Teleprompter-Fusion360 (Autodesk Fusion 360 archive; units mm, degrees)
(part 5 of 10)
sketch "Skizze56" plane through (0, 0, 0) normal (0, 0, -1) x axis (1, 0, 0)
  line L1 (-2.9969, -220.3404) -> (-2.9968, -220.3404)
  line L2 (-2.9969, -235.9451) -> (-2.9969, -220.3404)
  line L3 (-14.9969, -240.1877) -> (-7.2396, -240.1877)
  line L4 (-14.9969, -255.3404) -> (-14.9969, -240.1877)
  line L5 (374.0031, -255.3404) -> (-14.9969, -255.3404)
  line L6 (374.0031, -240.1877) -> (374.0031, -255.3404)
  line L7 (366.2457, -240.1877) -> (374.0031, -240.1877)
  line L8 (362.0031, -220.3404) -> (362.0031, -235.9451)
  line L9 (361.0031, -220.3404) -> (362.0031, -220.3404)
  line L10 (358.0031, -167.3404) -> (358.0031, -217.3404)
  line L11 (362.0031, -164.3404) -> (361.0031, -164.3404)
  line L12 (362.0031, -134.383) -> (362.0031, -164.3404)
  line L13 (374.0031, -130.1404) -> (366.2457, -130.1404)
  line L14 (374.0031, -95.9404) -> (374.0031, -130.1404)
  line L15 (366.2457, -95.9404) -> (374.0031, -95.9404)
  line L16 (362.0031, -65.983) -> (362.0031, -91.6977)
  line L17 (374.0031, -61.7404) -> (366.2457, -61.7404)
  line L18 (374.0031, -27.5404) -> (374.0031, -61.7404)
  line L19 (366.2457, -27.5404) -> (374.0031, -27.5404)
  line L20 (362.0031, 2.417) -> (362.0031, -23.2977)
  line L21 (374.0031, 6.6596) -> (366.2457, 6.6596)
  line L22 (-2.9969, 18.6596) -> (362.0031, 18.6596)
  line L23 (-7.2396, 6.6596) -> (-14.9969, 6.6596)
  line L24 (-2.9969, -23.2977) -> (-2.9969, 2.417)
  line L25 (-14.9969, -27.5404) -> (-7.2396, -27.5404)
  line L26 (-14.9969, -61.7404) -> (-14.9969, -27.5404)
  line L27 (-7.2396, -61.7404) -> (-14.9969, -61.7404)
  line L28 (-2.9969, -91.6977) -> (-2.9969, -65.983)
  line L29 (-14.9969, -95.9404) -> (-7.2396, -95.9404)
  line L30 (-14.9969, -130.1404) -> (-14.9969, -95.9404)
  line L31 (-7.2396, -130.1404) -> (-14.9969, -130.1404)
  line L32 (-2.9969, -164.3404) -> (-2.9969, -134.383)
  line L33 (-2.9968, -164.3404) -> (-2.9969, -164.3404)
  line L34 (0.0031, -217.3404) -> (0.0031, -167.3404)
  line L35 (300.0031, -190.3404) -> (300.0031, -174.3404)
  line L36 (203.5031, -202.3404) -> (288.0031, -202.3404)
  line L37 (191.5031, -174.3404) -> (191.5031, -190.3404)
  line L38 (288.0031, -162.3404) -> (203.5031, -162.3404)
  line L39 (191.5031, -31.3404) -> (191.5031, -114.3404)
  line L40 (312.0031, -19.3404) -> (203.5031, -19.3404)
  line L41 (324.0031, -114.3404) -> (324.0031, -31.3404)
  line L42 (203.5031, -126.3404) -> (312.0031, -126.3404)
  line L43 (71.0031, -202.3404) -> (155.5031, -202.3404)
  line L44 (59.0031, -174.3404) -> (59.0031, -190.3404)
  line L45 (155.5031, -162.3404) -> (71.0031, -162.3404)
  line L46 (167.5031, -190.3404) -> (167.5031, -174.3404)
  line L47 (47.0031, -126.3404) -> (155.5031, -126.3404)
  line L48 (35.0031, -31.3404) -> (35.0031, -114.3404)
  line L49 (155.5031, -19.3404) -> (47.0031, -19.3404)
  line L50 (167.5031, -114.3404) -> (167.5031, -31.3404)
  line L51 (-2.9969, -258.4937) -> (-2.9969, -220.3404)
  line L52 (-2.9969, -255.3404) -> (-14.9969, -255.3404)
  line L53 (-2.9969, -240.1877) -> (-2.9969, -255.3404)
  line L54 (-14.9969, -240.1877) -> (-2.9969, -240.1877)
  line L55 (-14.9969, -255.3404) -> (-14.9969, -240.1877)
  line L56 (362.0031, -255.3404) -> (362.0031, -235.9451)
  line L57 (374.0031, -240.1877) -> (362.0031, -240.1877)
  line L58 (374.0031, -255.3404) -> (374.0031, -240.1877)
  line L59 (362.0031, -255.3404) -> (374.0031, -255.3404)
  line L60 (362.0031, -240.1877) -> (362.0031, -255.3404)
  line L61 (368.0031, -240.1877) -> (368.0031, -255.3404)
  line L62 (-8.9969, -240.1877) -> (-8.9969, -255.3404)
  arc A1 centre (-5.1183, -238.0664) radius 3 clockwise from (-2.9969, -235.9451) to (-7.2396, -240.1877)
  arc A2 centre (364.1244, -238.0664) radius 3 clockwise from (366.2457, -240.1877) to (362.0031, -235.9451)
  arc A3 centre (361.0031, -217.3404) radius 3 clockwise from (361.0031, -220.3404) to (358.0031, -217.3404)
  arc A4 centre (361.0031, -167.3404) radius 3 clockwise from (358.0031, -167.3404) to (361.0031, -164.3404)
  arc A5 centre (364.1244, -132.2617) radius 3 clockwise from (362.0031, -134.383) to (366.2457, -130.1404)
  arc A6 centre (364.1244, -93.8191) radius 3 clockwise from (366.2457, -95.9404) to (362.0031, -91.6977)
  arc A7 centre (364.1244, -63.8617) radius 3 clockwise from (362.0031, -65.983) to (366.2457, -61.7404)
  arc A8 centre (364.1244, -25.4191) radius 3 clockwise from (366.2457, -27.5404) to (362.0031, -23.2977)
  arc A9 centre (364.1244, 4.5383) radius 3 clockwise from (362.0031, 2.417) to (366.2457, 6.6596)
  arc A10 centre (362.0031, 6.6596) radius 12 clockwise from (362.0031, 18.6596) to (374.0031, 6.6596)
  arc A11 centre (-2.9969, 6.6596) radius 12 clockwise from (-14.9969, 6.6596) to (-2.9969, 18.6596)
  arc A12 centre (-5.1183, 4.5383) radius 3 clockwise from (-7.2396, 6.6596) to (-2.9969, 2.417)
  arc A13 centre (-5.1183, -25.4191) radius 3 clockwise from (-2.9969, -23.2977) to (-7.2396, -27.5404)
  arc A14 centre (-5.1183, -63.8617) radius 3 clockwise from (-7.2396, -61.7404) to (-2.9969, -65.983)
  arc A15 centre (-5.1183, -93.8191) radius 3 clockwise from (-2.9969, -91.6977) to (-7.2396, -95.9404)
  arc A16 centre (-5.1183, -132.2617) radius 3 clockwise from (-7.2396, -130.1404) to (-2.9969, -134.383)
  arc A17 centre (-2.9969, -167.3404) radius 3 clockwise from (-2.9968, -164.3404) to (0.0031, -167.3404)
  arc A18 centre (-2.9969, -217.3404) radius 3 clockwise from (0.0031, -217.3404) to (-2.9968, -220.3404)
  circle C1 centre (-8.9969, -44.6404) radius 1.5
  circle C2 centre (368.0031, -44.6404) radius 1.5
  arc A19 centre (288.0031, -190.3404) radius 12 clockwise from (300.0031, -190.3404) to (288.0031, -202.3404)
  arc A20 centre (203.5031, -190.3404) radius 12 clockwise from (203.5031, -202.3404) to (191.5031, -190.3404)
  arc A21 centre (203.5031, -174.3404) radius 12 clockwise from (191.5031, -174.3404) to (203.5031, -162.3404)
  arc A22 centre (288.0031, -174.3404) radius 12 clockwise from (288.0031, -162.3404) to (300.0031, -174.3404)
  arc A23 centre (203.5031, -31.3404) radius 12 clockwise from (191.5031, -31.3404) to (203.5031, -19.3404)
  arc A24 centre (312.0031, -31.3404) radius 12 clockwise from (312.0031, -19.3404) to (324.0031, -31.3404)
  arc A25 centre (312.0031, -114.3404) radius 12 clockwise from (324.0031, -114.3404) to (312.0031, -126.3404)
  arc A26 centre (203.5031, -114.3404) radius 12 clockwise from (203.5031, -126.3404) to (191.5031, -114.3404)
  arc A27 centre (71.0031, -190.3404) radius 12 clockwise from (71.0031, -202.3404) to (59.0031, -190.3404)
  arc A28 centre (71.0031, -174.3404) radius 12 clockwise from (59.0031, -174.3404) to (71.0031, -162.3404)
  arc A29 centre (155.5031, -174.3404) radius 12 clockwise from (155.5031, -162.3404) to (167.5031, -174.3404)
  arc A30 centre (155.5031, -190.3404) radius 12 clockwise from (167.5031, -190.3404) to (155.5031, -202.3404)
  arc A31 centre (47.0031, -114.3404) radius 12 clockwise from (47.0031, -126.3404) to (35.0031, -114.3404)
  arc A32 centre (47.0031, -31.3404) radius 12 clockwise from (35.0031, -31.3404) to (47.0031, -19.3404)
  arc A33 centre (155.5031, -31.3404) radius 12 clockwise from (155.5031, -19.3404) to (167.5031, -31.3404)
  arc A34 centre (155.5031, -114.3404) radius 12 clockwise from (167.5031, -114.3404) to (155.5031, -126.3404)
  circle C3 centre (368.0031, -113.0404) radius 1.5
  circle C4 centre (-8.9969, -113.0404) radius 1.5
  circle C5 centre (-8.9969, -246.1877) radius 1.5
  circle C6 centre (368.0031, -246.1877) radius 1.5
  point P3 (-2.9969, -220.3404)
  point P124 (-2.9969, -220.3404)
  point P128 (-2.9969, -240.1877)
  point P8 (-14.9969, -255.3404)
  point P126 (-14.9969, -255.3404)
  point P12 (362.0031, -235.9451)
  point P130 (362.0031, -235.9451)
  point P9 (374.0031, -255.3404)
  point P133 (374.0031, -255.3404)
  point P131 (362.0031, -240.1877)
  point P135 (368.0031, -255.3404)
  point P136 (368.0031, -240.1877)
  point P137 (-8.9969, -255.3404)
  point P138 (-8.9969, -240.1877)
  point P139 (-8.9969, -246.1877)
  point P140 (368.0031, -246.1877)
  coincident P3 P124
  perpendicular L5 L51
  horizontal L52
  vertical L53
  horizontal L54
  vertical L55
  midpoint A1 P128
  coincident P8 P126
  coincident P12 P130
  perpendicular L5 L56
  horizontal L57
  vertical L58
  horizontal L59
  vertical L60
  coincident P9 P133
  midpoint A2 P131
  midpoint L59 P135
  midpoint L57 P136
  midpoint L52 P137
  midpoint L54 P138
  coincident L62 P139
  coincident L61 P140
  dimension "d331" diameter C5 = 3
  dimension "d332" diameter C6 = 3
  dimension "d333" distance L57 P140 = 6
  dimension "d334" distance L54 P139 = 6
extrude "Extrusion56" cut sketch "Skizze56" profile of C5 C6 against normal blind 12
sketch "Skizze57" plane through (-14.9969, 0, 0) normal (-1, 0, 0) x axis (0, -1, 0)
  line L1 (-156.4445, 183.2864) -> (-195.6625, 104.4333)
  line L2 (-133.7, 138.3075) -> (-133.7, 177.9426)
  line L3 (-176.4327, 90.6042) -> (-137.2147, 129.8223)
  line L4 (-45.7711, 251.1832) -> (-86.6874, 247.805)
  line L5 (-77.2147, 189.8223) -> (-36.2984, 230.7386)
  line L6 (-97.7, 235.8456) -> (-97.7, 198.3075)
  line L7 (-117.4574, 213.455) -> (-113.9426, 213.455)
  line L8 (-121.7, 240.7124) -> (-121.7, 217.6976)
  line L9 (-113.9426, 244.955) -> (-117.4574, 244.955)
  line L10 (-109.7, 217.6976) -> (-109.7, 240.7124)
  line L11 (-121.7, 177.7124) -> (-121.7, 154.6976)
  line L12 (-113.9426, 181.955) -> (-117.4574, 181.955)
  line L13 (-109.7, 154.6976) -> (-109.7, 177.7124)
  line L14 (-117.4574, 150.455) -> (-113.9426, 150.455)
  line L15 (-114.5768, 112.8622) -> (-167.9537, 59.4853)
  line L16 (-94.0916, 51) -> (-94.0916, 104.3769)
  line L17 (-159.4684, 39) -> (-106.0916, 39)
  line L18 (-240.1877, 0) -> (-240.1877, 7.7574)
  line L19 (-220.3404, 0) -> (-240.1877, 0)
  line L20 (-220.3404, 11.3932) -> (-220.3404, 0)
  line L21 (-169.9972, 16) -> (-214.6835, 16)
  line L22 (-164.3404, 0) -> (-164.3404, 11.3932)
  line L23 (-130.1404, 0) -> (-164.3404, 0)
  line L24 (-130.1404, 7.7574) -> (-130.1404, 0)
  line L25 (-100.183, 12) -> (-125.8977, 12)
  line L26 (-95.9404, 0) -> (-95.9404, 7.7574)
  line L27 (-61.7404, 0) -> (-95.9404, 0)
  line L28 (-61.7404, 7.7574) -> (-61.7404, 0)
  line L29 (-31.783, 12) -> (-57.4977, 12)
  line L30 (-27.5404, 0) -> (-27.5404, 7.7574)
  line L31 (6.6596, 0) -> (-27.5404, 0)
  line L32 (6.6596, 15) -> (6.6596, 0)
  line L33 (-58.0916, 27) -> (-5.3404, 27)
  line L34 (-70.0916, 152.3769) -> (-70.0916, 39)
  line L35 (15.1449, 242.5839) -> (-66.5768, 160.8622)
  line L36 (18.6596, 263) -> (18.6596, 251.0692)
  line L37 (0.4576, 267) -> (14.6596, 267)
  line L38 (-121.7, 256.955) -> (-0.5298, 266.9593)
  line L39 (-126.9563, 256.521) -> (-123.6681, 256.7925)
  line L40 (-255.037, 12) -> (-136.7133, 249.9055)
  line L41 (-244.4304, 12) -> (-255.037, 12)
  line L42 (-255.037, 12) -> (-247.7143, 26.7233)
  line L43 (-240.1877, 12) -> (-240.1877, 0)
  line L44 (-255.3404, 12) -> (-240.1877, 12)
  line L45 (-255.3404, 0) -> (-255.3404, 12)
  line L46 (-240.1877, 0) -> (-255.3404, 0)
  line L47 (-255.3404, 12) -> (-255.037, 12)
  line L48 (-255.3404, 24) -> (-255.3404, 12)
  line L49 (-243.1004, 36) -> (-243.3404, 36)
  line L50 (-234.7012, 52.8878) -> (-240.4466, 41.3358)
  line L51 (-240.4466, 41.3358) -> (-247.7143, 26.7233)
  circle C1 centre (-140.2404, 6) radius 1.5
  circle C2 centre (-115.7, 197.705) radius 1.5
  arc A1 centre (-184.918, 99.0895) radius 12 clockwise from (-176.4327, 90.6042) to (-195.6625, 104.4333)
  arc A2 centre (-145.7, 177.9426) radius 12 clockwise from (-156.4445, 183.2864) to (-133.7, 177.9426)
  arc A3 centre (-145.7, 138.3075) radius 12 clockwise from (-133.7, 138.3075) to (-137.2147, 129.8223)
  arc A4 centre (-85.7, 235.8456) radius 12 clockwise from (-97.7, 235.8456) to (-86.6874, 247.805)
  arc A5 centre (-44.7837, 239.2239) radius 12 clockwise from (-45.7711, 251.1832) to (-36.2984, 230.7386)
  arc A6 centre (-85.7, 198.3075) radius 12 clockwise from (-77.2147, 189.8223) to (-97.7, 198.3075)
  arc A7 centre (-119.5787, 215.5763) radius 3 clockwise from (-117.4574, 213.455) to (-121.7, 217.6976)
  arc A8 centre (-119.5787, 242.8337) radius 3 clockwise from (-121.7, 240.7124) to (-117.4574, 244.955)
  arc A9 centre (-111.8213, 242.8337) radius 3 clockwise from (-113.9426, 244.955) to (-109.7, 240.7124)
  arc A10 centre (-111.8213, 215.5763) radius 3 clockwise from (-109.7, 217.6976) to (-113.9426, 213.455)
  arc A11 centre (-119.5787, 179.8337) radius 3 clockwise from (-121.7, 177.7124) to (-117.4574, 181.955)
  arc A12 centre (-111.8213, 179.8337) radius 3 clockwise from (-113.9426, 181.955) to (-109.7, 177.7124)
  arc A13 centre (-111.8213, 152.5763) radius 3 clockwise from (-109.7, 154.6976) to (-113.9426, 150.455)
  arc A14 centre (-119.5787, 152.5763) radius 3 clockwise from (-117.4574, 150.455) to (-121.7, 154.6976)
  arc A15 centre (-106.0916, 104.3769) radius 12 clockwise from (-114.5768, 112.8622) to (-94.0916, 104.3769)
  arc A16 centre (-106.0916, 51) radius 12 clockwise from (-94.0916, 51) to (-106.0916, 39)
  arc A17 centre (-159.4684, 51) radius 12 clockwise from (-159.4684, 39) to (-167.9537, 59.4853)
  circle C3 centre (-230.2641, 6) radius 1.5
  circle C4 centre (-10.4404, 6) radius 1.5
  circle C5 centre (-78.8404, 6) radius 1.5
  arc A18 centre (-242.3091, 9.8787) radius 3 clockwise from (-244.4304, 12) to (-240.1877, 7.7574)
  arc A19 centre (-217.3404, 11.3932) radius 3 clockwise from (-220.3404, 11.3932) to (-219.9972, 12.7865)
  arc A20 centre (-214.6835, 10) radius 6 clockwise from (-219.9972, 12.7865) to (-214.6835, 16)
  arc A21 centre (-169.9972, 10) radius 6 clockwise from (-169.9972, 16) to (-164.6835, 12.7865)
  arc A22 centre (-167.3404, 11.3932) radius 3 clockwise from (-164.6835, 12.7865) to (-164.3404, 11.3932)
  arc A23 centre (-128.0191, 9.8787) radius 3 clockwise from (-130.1404, 7.7574) to (-125.8977, 12)
  arc A24 centre (-98.0617, 9.8787) radius 3 clockwise from (-100.183, 12) to (-95.9404, 7.7574)
  arc A25 centre (-59.6191, 9.8787) radius 3 clockwise from (-61.7404, 7.7574) to (-57.4977, 12)
  arc A26 centre (-29.6617, 9.8787) radius 3 clockwise from (-31.783, 12) to (-27.5404, 7.7574)
  arc A27 centre (-5.3404, 15) radius 12 clockwise from (-5.3404, 27) to (6.6596, 15)
  arc A28 centre (-58.0916, 39) radius 12 clockwise from (-58.0916, 27) to (-70.0916, 39)
  arc A29 centre (-58.0916, 152.3769) radius 12 clockwise from (-70.0916, 152.3769) to (-66.5768, 160.8622)
  arc A30 centre (6.6596, 251.0692) radius 12 clockwise from (18.6596, 251.0692) to (15.1449, 242.5839)
  arc A31 centre (14.6596, 263) radius 4 clockwise from (14.6596, 267) to (18.6596, 263)
  arc A32 centre (0.4576, 255) radius 12 clockwise from (-0.5298, 266.9593) to (0.4576, 267)
  arc A33 centre (-121.7, 244.955) radius 12 clockwise from (-123.6681, 256.7925) to (-121.7, 256.955)
  arc A34 centre (-125.9689, 244.5617) radius 12 clockwise from (-136.7133, 249.9055) to (-126.9563, 256.521)
  arc A35 centre (-243.3404, 24) radius 12 clockwise from (-255.3404, 24) to (-247.2657, 35.3398)
  arc A36 centre (-251.1911, 46.6796) radius 12 clockwise from (-240.4466, 41.3358) to (-247.2657, 35.3398)
  point P116 (-247.7143, 26.7233)
  point P115 (-255.037, 12)
  point P117 (-255.037, 12)
  point P122 (-255.037, 12)
  point P120 (-255.3404, 12)
  point P123 (-255.3404, 12)
  point P124 (-255.3404, 12)
  point P128 (-234.7012, 52.8878)
  point P130 (-240.4466, 41.3358)
  point P132 (-243.1004, 36)
  coincident L40 P116
  coincident P115 P117
  parallel L40 L42
  coincident P115 P122
  coincident P120 P123
  coincident P120 P124
  perpendicular L44 L48
  horizontal L49
  tangent L49 A35
  tangent L48 A35
  coincident L40 P128
  tangent A35 A36
  tangent L50 A36
  coincident L40 P130
  coincident L40 P132
  dimension "d337" distance L41 L49 = 24
  dimension "d338" radius A35 = 12
  dimension "d339" diameter A36 = 24
extrude "Extrusion57" add sketch "Skizze57" profile of L40 L42 L44 L47 L48 A35 A36 L51 against normal blind 12
sketch "Skizze58" plane through (374.0031, 0, 0) normal (1, 0, 0) x axis (0, 1, 0)
  line L1 (137.2147, 129.8223) -> (176.4327, 90.6042)
  line L2 (133.7, 177.9426) -> (133.7, 138.3075)
  line L3 (195.6625, 104.4333) -> (156.4445, 183.2864)
  line L4 (97.7, 198.3075) -> (97.7, 235.8456)
  line L5 (36.2984, 230.7386) -> (77.2147, 189.8223)
  line L6 (86.6874, 247.805) -> (45.7711, 251.1832)
  line L7 (113.9426, 213.455) -> (117.4574, 213.455)
  line L8 (109.7, 240.7124) -> (109.7, 217.6976)
  line L9 (117.4574, 244.955) -> (113.9426, 244.955)
  line L10 (121.7, 217.6976) -> (121.7, 240.7124)
  line L11 (121.7, 154.6976) -> (121.7, 177.7124)
  line L12 (113.9426, 150.455) -> (117.4574, 150.455)
  line L13 (109.7, 177.7124) -> (109.7, 154.6976)
  line L14 (117.4574, 181.955) -> (113.9426, 181.955)
  line L15 (167.9537, 59.4853) -> (114.5768, 112.8622)
  line L16 (106.0916, 39) -> (159.4684, 39)
  line L17 (94.0916, 104.3769) -> (94.0916, 51)
  line L18 (255.037, 12) -> (244.4304, 12)
  line L19 (136.7133, 249.9055) -> (255.037, 12)
  line L20 (123.6681, 256.7925) -> (126.9563, 256.521)
  line L21
  line L22 (-14.6596, 267) -> (-0.4576, 267)
  line L23 (-18.6596, 251.0692) -> (-18.6596, 263)
  line L24 (66.5768, 160.8622) -> (-15.1449, 242.5839)
  line L25 (70.0916, 39) -> (70.0916, 152.3769)
  line L26 (5.3404, 27) -> (58.0916, 27)
  line L27 (-6.6596, 0) -> (-6.6596, 15)
  line L28 (27.5404, 0) -> (-6.6596, 0)
  line L29 (27.5404, 7.7574) -> (27.5404, 0)
  line L30 (57.4977, 12) -> (31.783, 12)
  line L31 (61.7404, 0) -> (61.7404, 7.7574)
  line L32 (95.9404, 0) -> (61.7404, 0)
  line L33 (95.9404, 7.7574) -> (95.9404, 0)
  line L34 (125.8977, 12) -> (100.183, 12)
  line L35 (130.1404, 0) -> (130.1404, 7.7574)
  line L36 (164.3404, 0) -> (130.1404, 0)
  line L37 (164.3404, 11.3932) -> (164.3404, 0)
  line L38 (214.6835, 16) -> (169.9972, 16)
  line L39 (220.3404, 0) -> (220.3404, 11.3932)
  line L40 (240.1877, 0) -> (220.3404, 0)
  line L41 (240.1877, 7.7574) -> (240.1877, 0)
  line L42 (137.2147, 129.8223) -> (176.4327, 90.6042)
  line L43 (133.7, 177.9426) -> (133.7, 138.3075)
  line L44 (195.6625, 104.4333) -> (156.4445, 183.2864)
  line L45 (97.7, 198.3075) -> (97.7, 235.8456)
  line L46 (36.2984, 230.7386) -> (77.2147, 189.8223)
  line L47 (86.6874, 247.805) -> (45.7711, 251.1832)
  line L48 (113.9426, 213.455) -> (117.4574, 213.455)
  line L49 (109.7, 240.7124) -> (109.7, 217.6976)
  line L50 (117.4574, 244.955) -> (113.9426, 244.955)
  line L51 (121.7, 217.6976) -> (121.7, 240.7124)
  line L52 (121.7, 154.6976) -> (121.7, 177.7124)
  line L53 (113.9426, 150.455) -> (117.4574, 150.455)
  line L54 (109.7, 177.7124) -> (109.7, 154.6976)
  line L55 (117.4574, 181.955) -> (113.9426, 181.955)
  line L56 (255.3404, 12) -> (244.4304, 12)
  line L57 (255.3404, 24) -> (255.3404, 12)
  line L58 (136.7133, 249.9055) -> (240.4466, 41.3358)
  line L59 (123.6681, 256.7925) -> (126.9563, 256.521)
  line L60
  line L61 (-14.6596, 267) -> (-0.4576, 267)
  line L62 (239.478, 10.8712) -> (-16.2993, 266.6485)
  circle C1 centre (140.2404, 6) radius 1.5
  circle C2 centre (115.7, 197.705) radius 1.5
  arc A1 centre (184.918, 99.0895) radius 12 clockwise from (195.6625, 104.4333) to (176.4327, 90.6042)
  arc A2 centre (145.7, 138.3075) radius 12 clockwise from (137.2147, 129.8223) to (133.7, 138.3075)
  arc A3 centre (145.7, 177.9426) radius 12 clockwise from (133.7, 177.9426) to (156.4445, 183.2864)
  arc A4 centre (85.7, 235.8456) radius 12 clockwise from (86.6874, 247.805) to (97.7, 235.8456)
  arc A5 centre (85.7, 198.3075) radius 12 clockwise from (97.7, 198.3075) to (77.2147, 189.8223)
  arc A6 centre (44.7837, 239.2239) radius 12 clockwise from (36.2984, 230.7386) to (45.7711, 251.1832)
  arc A7 centre (111.8213, 215.5763) radius 3 clockwise from (113.9426, 213.455) to (109.7, 217.6976)
  arc A8 centre (111.8213, 242.8337) radius 3 clockwise from (109.7, 240.7124) to (113.9426, 244.955)
  arc A9 centre (119.5787, 242.8337) radius 3 clockwise from (117.4574, 244.955) to (121.7, 240.7124)
  arc A10 centre (119.5787, 215.5763) radius 3 clockwise from (121.7, 217.6976) to (117.4574, 213.455)
  arc A11 centre (119.5787, 152.5763) radius 3 clockwise from (121.7, 154.6976) to (117.4574, 150.455)
  arc A12 centre (111.8213, 152.5763) radius 3 clockwise from (113.9426, 150.455) to (109.7, 154.6976)
  arc A13 centre (111.8213, 179.8337) radius 3 clockwise from (109.7, 177.7124) to (113.9426, 181.955)
  arc A14 centre (119.5787, 179.8337) radius 3 clockwise from (117.4574, 181.955) to (121.7, 177.7124)
  arc A15 centre (159.4684, 51) radius 12 clockwise from (167.9537, 59.4853) to (159.4684, 39)
  arc A16 centre (106.0916, 51) radius 12 clockwise from (106.0916, 39) to (94.0916, 51)
  arc A17 centre (106.0916, 104.3769) radius 12 clockwise from (94.0916, 104.3769) to (114.5768, 112.8622)
  circle C3 centre (230.2641, 6) radius 1.5
  circle C4 centre (10.4404, 6) radius 1.5
  circle C5 centre (78.8404, 6) radius 1.5
  arc A18 centre (242.3091, 9.8787) radius 3 clockwise from (240.1877, 7.7574) to (244.4304, 12)
  arc A19 centre (125.9689, 244.5617) radius 12 clockwise from (126.9563, 256.521) to (136.7133, 249.9055)
  arc A20 centre (121.7, 244.955) radius 12 clockwise from (121.7, 256.955) to (123.6681, 256.7925)
  arc A21 centre (-0.4576, 255) radius 12 clockwise from (-0.4576, 267) to (0.5298, 266.9593)
  arc A22 centre (-14.6596, 263) radius 4 clockwise from (-18.6596, 263) to (-14.6596, 267)
  arc A23 centre (-6.6596, 251.0692) radius 12 clockwise from (-15.1449, 242.5839) to (-18.6596, 251.0692)
  arc A24 centre (58.0916, 152.3769) radius 12 clockwise from (66.5768, 160.8622) to (70.0916, 152.3769)
  arc A25 centre (58.0916, 39) radius 12 clockwise from (70.0916, 39) to (58.0916, 27)
  arc A26 centre (5.3404, 15) radius 12 clockwise from (-6.6596, 15) to (5.3404, 27)
  arc A27 centre (29.6617, 9.8787) radius 3 clockwise from (27.5404, 7.7574) to (31.783, 12)
  arc A28 centre (59.6191, 9.8787) radius 3 clockwise from (57.4977, 12) to (61.7404, 7.7574)
  arc A29 centre (98.0617, 9.8787) radius 3 clockwise from (95.9404, 7.7574) to (100.183, 12)
  arc A30 centre (128.0191, 9.8787) radius 3 clockwise from (125.8977, 12) to (130.1404, 7.7574)
  arc A31 centre (167.3404, 11.3932) radius 3 clockwise from (164.3404, 11.3932) to (164.6835, 12.7865)
  arc A32 centre (169.9972, 10) radius 6 clockwise from (164.6835, 12.7865) to (169.9972, 16)
  arc A33 centre (214.6835, 10) radius 6 clockwise from (214.6835, 16) to (219.9972, 12.7865)
  arc A34 centre (217.3404, 11.3932) radius 3 clockwise from (219.9972, 12.7865) to (220.3404, 11.3932)
  circle C6 centre (115.7, 197.705) radius 1.5
  arc A35 centre (145.7, 138.3075) radius 12 clockwise from (137.2147, 129.8223) to (133.7, 138.3075)
  arc A36 centre (145.7, 177.9426) radius 12 clockwise from (133.7, 177.9426) to (156.4445, 183.2864)
  arc A37 centre (184.918, 99.0895) radius 12 clockwise from (195.6625, 104.4333) to (176.4327, 90.6042)
  arc A38 centre (85.7, 198.3075) radius 12 clockwise from (97.7, 198.3075) to (77.2147, 189.8223)
  arc A39 centre (44.7837, 239.2239) radius 12 clockwise from (36.2984, 230.7386) to (45.7711, 251.1832)
  arc A40 centre (85.7, 235.8456) radius 12 clockwise from (86.6874, 247.805) to (97.7, 235.8456)
  arc A41 centre (111.8213, 215.5763) radius 3 clockwise from (113.9426, 213.455) to (109.7, 217.6976)
  arc A42 centre (111.8213, 242.8337) radius 3 clockwise from (109.7, 240.7124) to (113.9426, 244.955)
  arc A43 centre (119.5787, 242.8337) radius 3 clockwise from (117.4574, 244.955) to (121.7, 240.7124)
  arc A44 centre (119.5787, 215.5763) radius 3 clockwise from (121.7, 217.6976) to (117.4574, 213.455)
  arc A45 centre (119.5787, 152.5763) radius 3 clockwise from (121.7, 154.6976) to (117.4574, 150.455)
  arc A46 centre (111.8213, 152.5763) radius 3 clockwise from (113.9426, 150.455) to (109.7, 154.6976)
  arc A47 centre (111.8213, 179.8337) radius 3 clockwise from (109.7, 177.7124) to (113.9426, 181.955)
  arc A48 centre (119.5787, 179.8337) radius 3 clockwise from (117.4574, 181.955) to (121.7, 177.7124)
  arc A49 centre (242.3091, 9.8787) radius 3 clockwise from (239.478, 10.8712) to (244.4304, 12)
  arc A50 centre (243.3404, 24) radius 12 clockwise from (247.2657, 35.3398) to (255.3404, 24)
  arc A51 centre (251.1911, 46.6796) radius 12 clockwise from (247.2657, 35.3398) to (240.4466, 41.3358)
  arc A52 centre (125.9689, 244.5617) radius 12 clockwise from (126.9563, 256.521) to (136.7133, 249.9055)
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extrude "Extrusion58" add sketch "Skizze58" profile of L19 L56 L57 A50 A51 against normal blind 12
sketch "Skizze59" plane through (0, 121.7, 0) normal (0, 1, 0) x axis (-1, 0, 0)
  line L1 (2.9969, 256.955) -> (2.9969, 249.1976)
  line L2 (-362.0031, 256.955) -> (2.9969, 256.955)
  line L3 (-362.0031, 249.1976) -> (-362.0031, 256.955)
  line L4 (-374.0031, 244.955) -> (-366.2457, 244.955)
  line L5 (-374.0031, 213.455) -> (-374.0031, 244.955)
  line L6 (-366.2457, 213.455) -> (-374.0031, 213.455)
  line L7 (-362.0031, 186.1976) -> (-362.0031, 209.2124)
  line L8 (-374.0031, 181.955) -> (-366.2457, 181.955)
  line L9 (-374.0031, 150.455) -> (-374.0031, 181.955)
  line L10 (14.9969, 150.455) -> (-374.0031, 150.455)
  line L11 (14.9969, 181.955) -> (14.9969, 150.455)
  line L12 (7.2396, 181.955) -> (14.9969, 181.955)
  line L13 (2.9969, 209.2124) -> (2.9969, 186.1976)
  line L14 (14.9969, 213.455) -> (7.2396, 213.455)
  line L15 (14.9969, 244.955) -> (14.9969, 213.455)
  line L16 (7.2396, 244.955) -> (14.9969, 244.955)
  line L17 (-338.0031, 220.955) -> (-338.0031, 186.455)
  line L18 (-225.8891, 232.955) -> (-326.0031, 232.955)
  line L19 (-251.9038, 177.9697) -> (-217.4038, 212.4697)
  line L20 (-326.0031, 174.455) -> (-260.3891, 174.455)
  line L21 (-98.617, 174.455) -> (-33.0031, 174.455)
  line L22 (-141.6023, 212.4697) -> (-107.1023, 177.9697)
  line L23 (-33.0031, 232.955) -> (-133.117, 232.955)
  line L24 (-21.0031, 186.455) -> (-21.0031, 220.955)
  line L25 (-161.0025, 189.955) -> (-161.0025, 194.455)
  line L26 (-141.7525, 189.955) -> (-161.0025, 189.955)
  line L27 (-217.2525, 162.455) -> (-141.7525, 162.455)
  line L28 (-198.0025, 189.955) -> (-217.2525, 189.955)
  line L29 (-198.0025, 194.455) -> (-198.0025, 189.955)
  line L30 (-165.0025, 198.455) -> (-194.0025, 198.455)
  arc A1 centre (5.1183, 247.0763) radius 3 clockwise from (7.2396, 244.955) to (2.9969, 249.1976)
  arc A2 centre (-364.1244, 247.0763) radius 3 clockwise from (-362.0031, 249.1976) to (-366.2457, 244.955)
  arc A3 centre (-364.1244, 211.3337) radius 3 clockwise from (-366.2457, 213.455) to (-362.0031, 209.2124)
  arc A4 centre (-364.1244, 184.0763) radius 3 clockwise from (-362.0031, 186.1976) to (-366.2457, 181.955)
  arc A5 centre (5.1183, 184.0763) radius 3 clockwise from (7.2396, 181.955) to (2.9969, 186.1976)
  arc A6 centre (5.1183, 211.3337) radius 3 clockwise from (2.9969, 209.2124) to (7.2396, 213.455)
  arc A7 centre (-326.0031, 220.955) radius 12 clockwise from (-338.0031, 220.955) to (-326.0031, 232.955)
  arc A8 centre (-225.8891, 220.955) radius 12 clockwise from (-225.8891, 232.955) to (-217.4038, 212.4697)
  arc A9 centre (-260.3891, 186.455) radius 12 clockwise from (-251.9038, 177.9697) to (-260.3891, 174.455)
  arc A10 centre (-326.0031, 186.455) radius 12 clockwise from (-326.0031, 174.455) to (-338.0031, 186.455)
  arc A11 centre (-98.617, 186.455) radius 12 clockwise from (-98.617, 174.455) to (-107.1023, 177.9697)
  arc A12 centre (-133.117, 220.955) radius 12 clockwise from (-141.6023, 212.4697) to (-133.117, 232.955)
  arc A13 centre (-33.0031, 220.955) radius 12 clockwise from (-33.0031, 232.955) to (-21.0031, 220.955)
  arc A14 centre (-33.0031, 186.455) radius 12 clockwise from (-21.0031, 186.455) to (-33.0031, 174.455)
  arc A15 centre (-141.7525, 176.205) radius 13.75 clockwise from (-141.7525, 189.955) to (-141.7525, 162.455)
  arc A16 centre (-217.2525, 176.205) radius 13.75 clockwise from (-217.2525, 162.455) to (-217.2525, 189.955)
  arc A17 centre (-194.0025, 194.455) radius 4 clockwise from (-198.0025, 194.455) to (-194.0025, 198.455)
  arc A18 centre (-165.0025, 194.455) radius 4 clockwise from (-165.0025, 198.455) to (-161.0025, 194.455)
extrude "Extrusion59" add sketch "Skizze59" profile of L17 A7 L18 A8 L19 A9 L20 A10 L21 A11 L22 A12 L23 A13 L24 A14 against normal blind 12
copy_paste_bodies "Körper kopieren/einfügen1"
move "Verschieben1"
move "Verschieben2"
sketch "Skizze61" plane through (0, 121.7, 0) normal (0, 1, 0) x axis (-1, 0, 0)
  line L1 (2.9969, 256.955) -> (2.9969, 249.1976)
  line L2 (-362.0031, 256.955) -> (2.9969, 256.955)
  line L3 (-362.0031, 249.1976) -> (-362.0031, 256.955)
  line L4 (-374.0031, 244.955) -> (-366.2457, 244.955)
  line L5 (-374.0031, 213.455) -> (-374.0031, 244.955)
  line L6 (-366.2457, 213.455) -> (-374.0031, 213.455)
  line L7 (-362.0031, 186.1976) -> (-362.0031, 209.2124)
  line L8 (-374.0031, 181.955) -> (-366.2457, 181.955)
  line L9 (-374.0031, 150.455) -> (-374.0031, 181.955)
  line L10 (14.9969, 150.455) -> (-374.0031, 150.455)
  line L11 (14.9969, 181.955) -> (14.9969, 150.455)
  line L12 (7.2396, 181.955) -> (14.9969, 181.955)
  line L13 (2.9969, 209.2124) -> (2.9969, 186.1976)
  line L14 (14.9969, 213.455) -> (7.2396, 213.455)
  line L15 (14.9969, 244.955) -> (14.9969, 213.455)
  line L16 (7.2396, 244.955) -> (14.9969, 244.955)
  line L17 (-161.0025, 189.955) -> (-161.0025, 194.455)
  line L18 (-141.7525, 189.955) -> (-161.0025, 189.955)
  line L19 (-217.2525, 162.455) -> (-141.7525, 162.455)
  line L20 (-198.0025, 189.955) -> (-217.2525, 189.955)
  line L21 (-198.0025, 194.455) -> (-198.0025, 189.955)
  line L22 (-165.0025, 198.455) -> (-194.0025, 198.455)
  line L23 (-137.0031, 155.455) -> (-222.0031, 155.455)
  line L24 (-179.5031, 103.2762) -> (-179.5031, 256.955)
  line L25 (-167.0031, 232.455) -> (-192.0031, 232.455)
  line L26 (-222.0031, 150.455) -> (-222.0031, 202.455)
  line L27 (-137.0031, 150.455) -> (-137.0031, 202.455)
  arc A1 centre (5.1183, 247.0763) radius 3 clockwise from (7.2396, 244.955) to (2.9969, 249.1976)
  arc A2 centre (-364.1244, 247.0763) radius 3 clockwise from (-362.0031, 249.1976) to (-366.2457, 244.955)
  arc A3 centre (-364.1244, 211.3337) radius 3 clockwise from (-366.2457, 213.455) to (-362.0031, 209.2124)
  arc A4 centre (-364.1244, 184.0763) radius 3 clockwise from (-362.0031, 186.1976) to (-366.2457, 181.955)
  arc A5 centre (5.1183, 184.0763) radius 3 clockwise from (7.2396, 181.955) to (2.9969, 186.1976)
  arc A6 centre (5.1183, 211.3337) radius 3 clockwise from (2.9969, 209.2124) to (7.2396, 213.455)
  arc A7 centre (-141.7525, 176.205) radius 13.75 clockwise from (-141.7525, 189.955) to (-141.7525, 162.455)
  arc A8 centre (-217.2525, 176.205) radius 13.75 clockwise from (-217.2525, 162.455) to (-217.2525, 189.955)
  arc A9 centre (-194.0025, 194.455) radius 4 clockwise from (-198.0025, 194.455) to (-194.0025, 198.455)
  arc A10 centre (-165.0025, 194.455) radius 4 clockwise from (-165.0025, 198.455) to (-161.0025, 194.455)
  circle C1 centre (-179.5031, 189.955) radius 34.5
  circle C2 centre (-179.5031, 189.955) radius 42.5
  arc A11 centre (-192.0031, 202.455) radius 30 clockwise from (-222.0031, 202.455) to (-192.0031, 232.455)
  arc A12 centre (-167.0031, 202.455) radius 30 clockwise from (-167.0031, 232.455) to (-137.0031, 202.455)
  point P44 (-179.5031, 256.955)
  point P46 (-179.5031, 189.955)
  point P48 (-137.0031, 155.455)
  point P49 (-222.0031, 155.455)
  point P50 (-222.0031, 150.455)
  point P51 (-137.0031, 150.455)
  parallel L10 L23
  midpoint L2 P44
  perpendicular L2 L24
  coincident L24 P46
  tangent L23 C1
  concentric C1 C2
  horizontal L25
  tangent C2 L25
  perpendicular L25 L26
  tangent C2 L26
  vertical L27
  tangent C2 L27
  coincident L27 P48
  coincident L26 P49
  coincident L10 P50
  coincident L10 P51
  tangent L26 A11
  tangent L25 A11
  tangent L25 A12
  tangent L27 A12
  dimension "d347" distance L10 L23 = 5
  dimension "d348" diameter C1 = 69
  dimension "d349" diameter C2 = 85
  dimension "d351" radius A11 = 30
  dimension "d352" radius A12 = 30
extrude "Extrusion60" cut sketch "Skizze61" profile of L10 L17 L18 A7 L19 A8 L20 L21 A9 L22 A10 L25 L26 L27 A11 A12 against normal blind 30
sketch "Skizze62" plane through (0, 121.7, 0) normal (0, 1, 0) x axis (-1, 0, 0)
  line L1 (-137.0031, 150.455) -> (-137.0031, 163.3013)
  line L2 (14.9969, 150.455) -> (-137.0031, 150.455)
  line L3 (14.9969, 181.955) -> (14.9969, 150.455)
  line L4 (7.2396, 181.955) -> (14.9969, 181.955)
  line L5 (2.9969, 209.2124) -> (2.9969, 186.1976)
  line L6 (14.9969, 213.455) -> (7.2396, 213.455)
  line L7 (14.9969, 244.955) -> (14.9969, 213.455)
  line L8 (7.2396, 244.955) -> (14.9969, 244.955)
  line L9 (2.9969, 256.955) -> (2.9969, 249.1976)
  line L10 (-362.0031, 256.955) -> (2.9969, 256.955)
  line L11 (-362.0031, 249.1976) -> (-362.0031, 256.955)
  line L12 (-374.0031, 244.955) -> (-366.2457, 244.955)
  line L13 (-374.0031, 213.455) -> (-374.0031, 244.955)
  line L14 (-366.2457, 213.455) -> (-374.0031, 213.455)
  line L15 (-362.0031, 186.1976) -> (-362.0031, 209.2124)
  line L16 (-374.0031, 181.955) -> (-366.2457, 181.955)
  line L17 (-374.0031, 150.455) -> (-374.0031, 181.955)
  line L18 (-222.0031, 150.455) -> (-374.0031, 150.455)
  line L19 (-222.0031, 163.3017) -> (-222.0031, 150.455)
  line L20 (-222.0031, 202.455) -> (-222.0031, 189.1083)
  line L21 (-167.0031, 232.455) -> (-192.0031, 232.455)
  line L22 (-137.0031, 189.1087) -> (-137.0031, 202.455)
  line L23 (-63.4671, 138.455) -> (-298.0031, 138.455)
  line L24 (-70.4725, 150.455) -> (-292.0525, 150.455)
  line L25 (-272.0031, 150.455) -> (-272.0031, 256.955)
  line L26 (-87.0031, 150.455) -> (-87.0031, 256.955)
  line L27 (-247.0031, 166.8096) -> (-247.0031, 245.1453)
  line L28 (-112.0031, 162.9375) -> (-112.0031, 244.2518)
  line L29 (-179.5031, 175.4474) -> (-179.5031, 256.955)
  line L30 (-222.0031, 150.455) -> (-222.0031, 202.455)
  line L31 (-137.0031, 202.455) -> (-137.0031, 150.455)
  arc A1 centre (5.1183, 184.0763) radius 3 clockwise from (7.2396, 181.955) to (2.9969, 186.1976)
  arc A2 centre (5.1183, 211.3337) radius 3 clockwise from (2.9969, 209.2124) to (7.2396, 213.455)
  arc A3 centre (5.1183, 247.0763) radius 3 clockwise from (7.2396, 244.955) to (2.9969, 249.1976)
  arc A4 centre (-364.1244, 247.0763) radius 3 clockwise from (-362.0031, 249.1976) to (-366.2457, 244.955)
  arc A5 centre (-364.1244, 211.3337) radius 3 clockwise from (-366.2457, 213.455) to (-362.0031, 209.2124)
  arc A6 centre (-364.1244, 184.0763) radius 3 clockwise from (-362.0031, 186.1976) to (-366.2457, 181.955)
  arc A7 centre (-217.2525, 176.205) radius 13.75 clockwise from (-222.0031, 163.3017) to (-222.0031, 189.1083)
  arc A8 centre (-192.0031, 202.455) radius 30 clockwise from (-222.0031, 202.455) to (-192.0031, 232.455)
  arc A9 centre (-167.0031, 202.455) radius 30 clockwise from (-167.0031, 232.455) to (-137.0031, 202.455)
  arc A10 centre (-141.7525, 176.205) radius 13.75 clockwise from (-137.0031, 189.1087) to (-137.0031, 163.3013)
  circle C1 centre (-247.0031, 231.955) radius 2
  circle C2 centre (-247.0031, 191.955) radius 2
  circle C3 centre (-112.0031, 231.955) radius 2
  circle C4 centre (-112.0031, 191.955) radius 2
  point P46 (-292.0525, 150.455)
  point P47 (-70.4725, 150.455)
  point P48 (-272.0031, 256.955)
  point P49 (-272.0031, 150.455)
  point P50 (-87.0031, 256.955)
  point P51 (-87.0031, 150.455)
  point P56 (-247.0031, 231.955)
  point P57 (-247.0031, 191.955)
  point P58 (-179.5031, 256.955)
  point P36 (-222.0031, 202.455)
  point P62 (-222.0031, 202.455)
  point P32 (-222.0031, 150.455)
  point P63 (-222.0031, 150.455)
  point P3 (-137.0031, 150.455)
  point P64 (-137.0031, 150.455)
  point P40 (-137.0031, 202.455)
  point P65 (-137.0031, 202.455)
  perpendicular L1 L23
  coincident L18 P46
  coincident L2 P47
  coincident L10 P48
  coincident L24 P49
  coincident L10 P50
  coincident L2 P51
  parallel L22 L26
  parallel L20 L25
  vertical L27
  parallel L26 L28
  coincident L27 P56
  coincident L27 P57
  midpoint L10 P58
  perpendicular L10 L29
  symmetric C1 L29 C3
  symmetric C2 L29 C4
  coincident P36 P62
  coincident P32 P63
  coincident P3 P64
  coincident P40 P65
  dimension "d356" distance L23 L24 = 12
  dimension "d357" distance L22 L26 = 50
  dimension "d358" distance L20 L25 = 50
  dimension "d359" distance L25 L27 = 25
  dimension "d360" distance L26 L28 = 25
  dimension "d361" diameter C1 = 4
  dimension "d362" diameter C2 = 4
  dimension "d363" distance L10 P56 = 25
  dimension "d364" distance L10 P57 = 65
extrude "Extrusion61" new body sketch "Skizze62" profile of L1 L2 L10 L18 L19 A7 L20 A8 L21 A9 L22 A10 L24 L25 L26 C1 C2 C3 C4 L30 L31 along normal blind 12
sketch "Skizze63" plane through (0, 121.7, 0) normal (0, 1, 0) x axis (-1, 0, 0)
  line L1 (-137.0031, 150.455) -> (-137.0031, 163.3013)
  line L2 (14.9969, 150.455) -> (-137.0031, 150.455)
  line L3 (14.9969, 181.955) -> (14.9969, 150.455)
  line L4 (7.2396, 181.955) -> (14.9969, 181.955)
  line L5 (2.9969, 209.2124) -> (2.9969, 186.1976)
  line L6 (14.9969, 213.455) -> (7.2396, 213.455)
  line L7 (14.9969, 244.955) -> (14.9969, 213.455)
  line L8 (7.2396, 244.955) -> (14.9969, 244.955)
  line L9 (2.9969, 256.955) -> (2.9969, 249.1976)
  line L10 (-362.0031, 256.955) -> (2.9969, 256.955)
  line L11 (-362.0031, 249.1976) -> (-362.0031, 256.955)
  line L12 (-374.0031, 244.955) -> (-366.2457, 244.955)
  line L13 (-374.0031, 213.455) -> (-374.0031, 244.955)
  line L14 (-366.2457, 213.455) -> (-374.0031, 213.455)
  line L15 (-362.0031, 186.1976) -> (-362.0031, 209.2124)
  line L16 (-374.0031, 181.955) -> (-366.2457, 181.955)
  line L17 (-374.0031, 150.455) -> (-374.0031, 181.955)
  line L18 (-222.0031, 150.455) -> (-374.0031, 150.455)
  line L19 (-222.0031, 163.3017) -> (-222.0031, 150.455)
  line L20 (-222.0031, 202.455) -> (-222.0031, 189.1083)
  line L21 (-167.0031, 232.455) -> (-192.0031, 232.455)
  line L22 (-137.0031, 189.1087) -> (-137.0031, 202.455)
  arc A1 centre (5.1183, 184.0763) radius 3 clockwise from (7.2396, 181.955) to (2.9969, 186.1976)
  arc A2 centre (5.1183, 211.3337) radius 3 clockwise from (2.9969, 209.2124) to (7.2396, 213.455)
  arc A3 centre (5.1183, 247.0763) radius 3 clockwise from (7.2396, 244.955) to (2.9969, 249.1976)
  arc A4 centre (-364.1244, 247.0763) radius 3 clockwise from (-362.0031, 249.1976) to (-366.2457, 244.955)
  arc A5 centre (-364.1244, 211.3337) radius 3 clockwise from (-366.2457, 213.455) to (-362.0031, 209.2124)
  arc A6 centre (-364.1244, 184.0763) radius 3 clockwise from (-362.0031, 186.1976) to (-366.2457, 181.955)
  arc A7 centre (-217.2525, 176.205) radius 13.75 clockwise from (-222.0031, 163.3017) to (-222.0031, 189.1083)
  arc A8 centre (-192.0031, 202.455) radius 30 clockwise from (-222.0031, 202.455) to (-192.0031, 232.455)
  arc A9 centre (-167.0031, 202.455) radius 30 clockwise from (-167.0031, 232.455) to (-137.0031, 202.455)
  arc A10 centre (-141.7525, 176.205) radius 13.75 clockwise from (-137.0031, 189.1087) to (-137.0031, 163.3013)
  circle C1 centre (-112.0031, 231.955) radius 2
  circle C2 centre (-112.0031, 191.955) radius 2
  circle C3 centre (-247.0031, 231.955) radius 2
  circle C4 centre (-247.0031, 191.955) radius 2
extrude "Extrusion62" cut sketch "Skizze63" profile of C1 C2 C3 C4 against normal blind 20
extrude "Extrusion63" new body of existing geometry blind 12
combine "Kombinieren1"
sketch "Skizze64" plane through (0, 133.7, 0) normal (0, 1, 0) x axis (-1, 0, 0)
  line L1 (-272.0031, 256.955) -> (-87.0031, 256.955)
  line L2 (-272.0031, 138.455) -> (-272.0031, 256.955)
  line L3 (-222.0031, 138.455) -> (-272.0031, 138.455)
  line L4 (-222.0031, 202.455) -> (-222.0031, 138.455)
  line L5 (-167.0031, 232.455) -> (-192.0031, 232.455)
  line L6 (-137.0031, 138.455) -> (-137.0031, 202.455)
  line L7 (-87.0031, 138.455) -> (-137.0031, 138.455)
  line L8 (-87.0031, 256.955) -> (-87.0031, 138.455)
  line L9 (-137.0031, 150.455) -> (-137.0031, 163.3013)
  line L10 (14.9969, 150.455) -> (-137.0031, 150.455)
  line L11 (14.9969, 181.955) -> (14.9969, 150.455)
  line L12 (7.2396, 181.955) -> (14.9969, 181.955)
  line L13 (2.9969, 209.2124) -> (2.9969, 186.1976)
  line L14 (14.9969, 213.455) -> (7.2396, 213.455)
  line L15 (14.9969, 244.955) -> (14.9969, 213.455)
  line L16 (7.2396, 244.955) -> (14.9969, 244.955)
  line L17 (2.9969, 256.955) -> (2.9969, 249.1976)
  line L18 (-362.0031, 256.955) -> (2.9969, 256.955)
  line L19 (-362.0031, 249.1976) -> (-362.0031, 256.955)
  line L20 (-374.0031, 244.955) -> (-366.2457, 244.955)
  line L21 (-374.0031, 213.455) -> (-374.0031, 244.955)
  line L22 (-366.2457, 213.455) -> (-374.0031, 213.455)
  line L23 (-362.0031, 186.1976) -> (-362.0031, 209.2124)
  line L24 (-374.0031, 181.955) -> (-366.2457, 181.955)
  line L25 (-374.0031, 150.455) -> (-374.0031, 181.955)
  line L26 (-222.0031, 150.455) -> (-374.0031, 150.455)
  line L27 (-222.0031, 163.3017) -> (-222.0031, 150.455)
  line L28 (-222.0031, 202.455) -> (-222.0031, 189.1083)
  line L29 (-167.0031, 232.455) -> (-192.0031, 232.455)
  line L30 (-137.0031, 189.1087) -> (-137.0031, 202.455)
  circle C1 centre (-247.0031, 191.955) radius 2
  circle C2 centre (-247.0031, 231.955) radius 2
  circle C3 centre (-112.0031, 231.955) radius 2
  circle C4 centre (-112.0031, 191.955) radius 2
  arc A1 centre (-192.0031, 202.455) radius 30 clockwise from (-222.0031, 202.455) to (-192.0031, 232.455)
  arc A2 centre (-167.0031, 202.455) radius 30 clockwise from (-167.0031, 232.455) to (-137.0031, 202.455)
  circle C5 centre (-247.0031, 191.955) radius 2
  circle C6 centre (-112.0031, 191.955) radius 2
  circle C7 centre (-247.0031, 231.955) radius 2
  circle C8 centre (-112.0031, 231.955) radius 2
  arc A3 centre (5.1183, 184.0763) radius 3 clockwise from (7.2396, 181.955) to (2.9969, 186.1976)
  arc A4 centre (5.1183, 211.3337) radius 3 clockwise from (2.9969, 209.2124) to (7.2396, 213.455)
  arc A5 centre (5.1183, 247.0763) radius 3 clockwise from (7.2396, 244.955) to (2.9969, 249.1976)
  arc A6 centre (-364.1244, 247.0763) radius 3 clockwise from (-362.0031, 249.1976) to (-366.2457, 244.955)
  arc A7 centre (-364.1244, 211.3337) radius 3 clockwise from (-366.2457, 213.455) to (-362.0031, 209.2124)
  arc A8 centre (-364.1244, 184.0763) radius 3 clockwise from (-362.0031, 186.1976) to (-366.2457, 181.955)
  arc A9 centre (-217.2525, 176.205) radius 13.75 clockwise from (-222.0031, 163.3017) to (-222.0031, 189.1083)
  arc A10 centre (-192.0031, 202.455) radius 30 clockwise from (-222.0031, 202.455) to (-192.0031, 232.455)
  arc A11 centre (-167.0031, 202.455) radius 30 clockwise from (-167.0031, 232.455) to (-137.0031, 202.455)
  arc A12 centre (-141.7525, 176.205) radius 13.75 clockwise from (-137.0031, 189.1087) to (-137.0031, 163.3013)
extrude "Extrusion64" new body sketch "Skizze64" profile of L2 L3 L4 L6 L7 L8 L10 L26 along normal blind 160
sketch "Skizze65" plane through (0, 0, 138.455) normal (0, 0, -1) x axis (1, 0, 0)
  line L1 (87.0031, -133.7) -> (137.0031, -133.7)
  line L2 (87.0031, -293.7) -> (87.0031, -133.7)
  line L3 (137.0031, -293.7) -> (87.0031, -293.7)
  line L4 (137.0031, -133.7) -> (137.0031, -293.7)
  line L5 (272.0031, -121.7) -> (87.0031, -121.7)
  line L6 (272.0031, -133.7) -> (272.0031, -121.7)
  line L7 (87.0031, -133.7) -> (272.0031, -133.7)
  line L8 (87.0031, -121.7) -> (87.0031, -133.7)
  line L9 (137.0031, -133.7) -> (87.0031, -133.7)
  line L10 (137.0031, -293.7) -> (137.0031, -133.7)
  line L11 (87.0031, -293.7) -> (137.0031, -293.7)
  line L12 (87.0031, -133.7) -> (87.0031, -293.7)
  line L13 (272.0031, -133.7) -> (222.0031, -133.7)
  line L14 (272.0031, -293.7) -> (272.0031, -133.7)
  line L15 (222.0031, -293.7) -> (272.0031, -293.7)
  line L16 (222.0031, -133.7) -> (222.0031, -293.7)
  line L17 (137.0031, -221.7) -> (222.0031, -221.7)
  line L18 (137.0031, -221.7) -> (222.0031, -221.7)
  line L19 (137.0031, -133.7) -> (137.0031, -221.7)
  line L20 (222.0031, -133.7) -> (137.0031, -133.7)
  line L21 (222.0031, -221.7) -> (222.0031, -133.7)
  line L22 (137.0031, -293.7) -> (222.0031, -293.7)
  line L23 (137.0031, -221.7) -> (137.0031, -293.7)
  line L24 (222.0031, -221.7) -> (137.0031, -221.7)
  line L25 (222.0031, -293.7) -> (222.0031, -221.7)
  point P18 (222.0031, -221.7)
  point P19 (137.0031, -221.7)
  point P11 (137.0031, -133.7)
  point P21 (137.0031, -133.7)
  point P17 (222.0031, -293.7)
  point P23 (222.0031, -293.7)
  coincident L16 P18
  coincident L10 P19
  perpendicular L10 L17
  horizontal L18
  vertical L19
  horizontal L20
  vertical L21
  coincident P11 P21
  horizontal L22
  vertical L23
  horizontal L24
  vertical L25
  coincident P17 P23
  dimension "d373" distance L5 L17 = 100
extrude "Extrusion65" add sketch "Skizze65" profile of L4 L10 L16 L17 L18 L22 L23 L24 L25 against normal blind 12
sketch "Skizze66" plane through (0, 0, 150.455) normal (0, 0, 1) x axis (-1, 0, 0)
  line L1 (-137.0031, -133.7) -> (-87.0031, -133.7)
  line L2 (-137.0031, -221.7) -> (-137.0031, -133.7)
  line L3 (-222.0031, -133.7) -> (-222.0031, -221.7)
  line L4 (-272.0031, -133.7) -> (-222.0031, -133.7)
  line L5 (-272.0031, -293.7) -> (-272.0031, -133.7)
  line L6 (-87.0031, -293.7) -> (-272.0031, -293.7)
  line L7 (-87.0031, -133.7) -> (-87.0031, -293.7)
  line L8 (-137.0031, -293.7) -> (-137.0031, -221.7)
  line L9 (-222.0031, -293.7) -> (-222.0031, -221.7)
  line L10 (-87.0031, -133.7) -> (-137.0031, -221.7)
  line L11 (-272.0031, -133.7) -> (-222.0031, -221.7)
  line L12 (-243.2495, -133.7) -> (-193.2495, -221.7)
  line L13 (-115.7566, -133.7) -> (-165.7566, -221.7)
  line L14 (-222.0031, -221.7) -> (-137.0031, -221.7)
  point P4 (-137.0031, -221.7)
  point P10 (-137.0031, -221.7)
  point P5 (-222.0031, -221.7)
  point P11 (-222.0031, -221.7)
  point P12 (-222.0031, -293.7)
  point P13 (-137.0031, -293.7)
  point P2 (-87.0031, -133.7)
  point P14 (-87.0031, -133.7)
  point P15 (-222.0031, -221.7)
  point P7 (-272.0031, -133.7)
  point P16 (-272.0031, -133.7)
  point P19 (-115.7566, -133.7)
  point P20 (-243.2495, -133.7)
  coincident P4 P10
  coincident P5 P11
  coincident L6 P12
  coincident L6 P13
  coincident P2 P14
  coincident P5 P15
  coincident P7 P16
  parallel L10 L13
  parallel L11 L12
  coincident L1 P19
  coincident L4 P20
extrude "Extrusion66" cut sketch "Skizze66" profile of L5 L6 L7 L8 L9 L10 L11 against normal blind 40
sketch "Skizze67" plane through (0, 0, 150.455) normal (0, 0, 1) x axis (-1, 0, 0)
  line L1 (-222.0031, -221.7) -> (-137.0031, -221.7)
  line L2 (-137.0031, -293.7) -> (-222.0031, -293.7)
  line L3 (-87.0031, -133.7) -> (-137.0031, -221.7)
  line L4 (-137.0031, -133.7) -> (-87.0031, -133.7)
  line L5 (-137.0031, -221.7) -> (-137.0031, -133.7)
  line L6 (-222.0031, -221.7) -> (-272.0031, -133.7)
  line L7 (-222.0031, -133.7) -> (-222.0031, -221.7)
  line L8 (-272.0031, -133.7) -> (-222.0031, -133.7)
  line L9 (-137.0031, -133.7) -> (-179.5031, -221.7)
  line L10 (-222.0031, -133.7) -> (-179.5031, -221.7)
  line L11 (-137.0031, -221.7) -> (-137.0031, -293.7)
  line L12 (-222.0031, -293.7) -> (-222.0031, -221.7)
  point P12 (-179.5031, -221.7)
  point P8 (-137.0031, -133.7)
  point P13 (-137.0031, -133.7)
  point P11 (-222.0031, -133.7)
  point P14 (-222.0031, -133.7)
  midpoint L1 P12
  coincident P8 P13
  coincident P11 P14
extrude "Extrusion67" new body sketch "Skizze67" profile of L1 L5 L7 L9 L10 against normal blind 12
fillet "Abrundung12" radius 15
extrude "Extrusion68" add of existing geometry blind 30
sketch "Skizze68" plane through (0, 0, 138.455) normal (0, 0, -1) x axis (1, 0, 0)
  line L1 (222.0031, -323.7) -> (137.0031, -323.7)
  line L2 (272.0031, -121.7) -> (272.0031, -133.7)
  line L3 (87.0031, -121.7) -> (137.0031, -121.7)
  line L4 (222.0031, -133.7) -> (222.0031, -121.7)
  line L5 (137.0031, -121.7) -> (137.0031, -133.7)
  line L6 (87.0031, -133.7) -> (87.0031, -121.7)
  line L7 (137.0031, -323.7) -> (222.0031, -323.7)
  line L8 (137.0031, -311.7) -> (137.0031, -323.7)
  line L9 (222.0031, -311.7) -> (137.0031, -311.7)
  line L10 (222.0031, -323.7) -> (222.0031, -311.7)
  line L11 (137.0031, -133.7) -> (87.0031, -133.7)
  line L12 (137.0031, -323.7) -> (137.0031, -221.7)
  line L13 (222.0031, -221.7) -> (222.0031, -323.7)
  line L14 (137.0031, -221.7) -> (222.0031, -221.7)
  line L15 (222.0031, -121.7) -> (272.0031, -121.7)
  line L16 (272.0031, -133.7) -> (222.0031, -133.7)
  point P4 (222.0031, -323.7)
  point P12 (222.0031, -323.7)
  point P15 (222.0031, -311.7)
  horizontal L7
  vertical L8
  horizontal L9
  vertical L10
  coincident P4 P12
  dimension "d386" distance P12 P15 = 12
extrude "Extrusion69" new body sketch "Skizze68" profile of L1 L7 L8 L9 L10 along normal blind 140 bodies "Back Brace of Camera Holder"
combine "Kombinieren2"
fillet "Abrundung13" radius 24
sketch "Skizze69" plane through (0, 255.3404, 0) normal (0, 1, 0) x axis (-1, 0, 0)
  line L1 (14.9969, 0) -> (-374.0031, 0)
  line L2 (14.9969, 12) -> (14.9969, 0)
  line L3 (-374.0031, 12) -> (14.9969, 12)
  line L4 (-374.0031, 0) -> (-374.0031, 12)
  line L5 (-222.0031, 138.455) -> (-137.0031, 138.455)
  line L6 (-222.0031, -1.545) -> (-222.0031, 138.455)
  line L7 (-137.0031, -1.545) -> (-222.0031, -1.545)
  line L8 (-137.0031, 138.455) -> (-137.0031, -1.545)
extrude "Extrusion70" add sketch "Skizze69" profile of L1 L3 L6 L8 along normal blind 56.359
fillet "Abrundung14" radius 24
fillet "Abrundung15" radius 24
fillet "Abrundung16" radius 24
fillet "Abrundung17" radius 24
